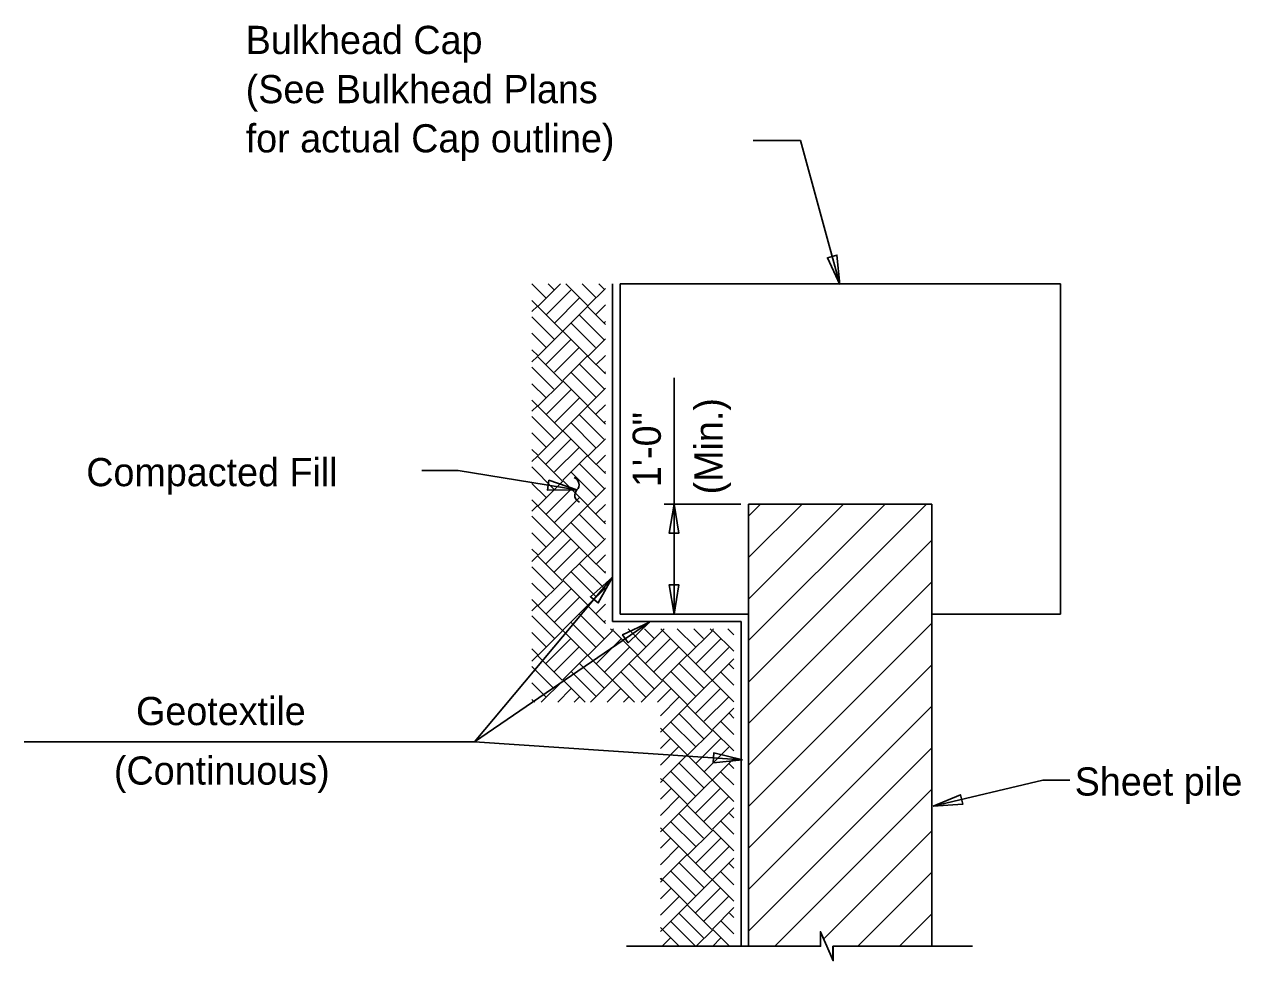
# Model space of a CAD drawing. Extents: x 0.4 to 30.4, y 0.1 to 19.4.
# Drawn here: x 8.54 to 15.06, y 14.4 to 19.42 of the extents above; entities that cross this region are included whole.
import ezdxf

# ---------------------------------------------------------------- set-up
doc = ezdxf.new("R2010")
doc.units = 0
for name, color, linetype in [('Dimension', 7, 'Continuous'), ('Miscellaneous', 7, 'Continuous'), ('Rebar', 7, 'Continuous'), ('SheetPileConc', 7, 'Continuous'), ('SheetPileConc_h', 7, 'Continuous'), ('TextStructures', 7, 'Continuous')]:
    doc.layers.add(name, color=color, linetype=linetype)

msp = doc.modelspace()

# ---------------------------------------------------------------- linework, layer by layer
at = {"layer": 'Dimension'}
for p, q in [((12.0243, 16.2579), (12.0243, 17.526)), ((12.3831, 16.8485), (11.9719, 16.8485)), ((11.8922, 16.2141), (10.9542, 15.5723)), ((12.3913, 15.4765), (10.9542, 15.5723)), ((11.7699, 14.4758), (12.738, 14.4758)), ((12.9487, 14.4758), (13.6252, 14.4758))]:
    msp.add_line(p, q, dxfattribs=at)
for points in [[(12.913, 18.0264), (12.7019, 18.7989), (12.4481, 18.7989)], [(11.5034, 16.9244), (10.8661, 17.0282), (10.6716, 17.0282)], [(11.6942, 16.4565), (10.9542, 15.5723), (8.5393, 15.5723)], [(13.4152, 15.2266), (14.0033, 15.3663), (14.1471, 15.3663)], [(12.738, 14.4758), (12.8099, 14.4758), (12.8099, 14.5539), (12.8768, 14.4028), (12.8768, 14.4758), (12.9487, 14.4758)], [(12.7383, 14.4758), (12.8108, 14.4758), (12.8108, 14.5533), (12.8446, 14.4758), (12.8783, 14.3983), (12.8783, 14.4758), (12.9508, 14.4758)]]:
    msp.add_lwpolyline(points, dxfattribs=at)
for points in [[(12.913, 18.0264), (12.8979, 18.1841), (12.8468, 18.1703)], [(11.5034, 16.9244), (11.3535, 16.9757), (11.345, 16.9234)], [(12.0243, 16.8485), (11.9978, 16.6923), (12.0507, 16.6923)], [(11.6942, 16.4565), (11.5762, 16.3508), (11.6176, 16.3178)], [(12.0243, 16.2579), (12.0507, 16.4141), (11.9978, 16.4141)], [(11.8922, 16.2141), (11.7485, 16.1474), (11.7785, 16.1038)], [(12.3913, 15.4765), (12.2372, 15.513), (12.2338, 15.4601)], [(13.4152, 15.2267), (13.5733, 15.2372), (13.561, 15.2886)]]:
    msp.add_lwpolyline(points, close=True, dxfattribs=at)
for centre, start, end in [((11.4742, 16.9527), 316.04656, 67.77378), ((11.5327, 16.8962), 136.04656, 247.77378)]:
    msp.add_arc(centre, 0.0406, start, end, dxfattribs=at)
at = {"layer": 'Miscellaneous'}
for p, q in [((11.2621, 18.0293), (11.3361, 17.9553)), ((11.4162, 18.0298), (11.2947, 17.9082)), ((11.3499, 18.0298), (11.3803, 17.9994)), ((11.5624, 17.9114), (11.444, 18.0298)), ((11.6065, 17.9555), (11.5323, 18.0298)), ((11.6507, 17.9998), (11.6208, 18.0298)), ((11.4716, 17.9966), (11.3389, 17.8639)), ((11.5157, 17.9524), (11.383, 17.8198)), ((11.6559, 18.0048), (11.5624, 17.9114)), ((11.2919, 17.911), (11.2621, 17.9408)), ((11.2919, 17.911), (11.2621, 17.8812)), ((11.5594, 17.6434), (11.2947, 17.9082)), ((11.5596, 17.9086), (11.2948, 17.6438)), ((11.5596, 17.9086), (11.6559, 17.8123)), ((11.6559, 17.9166), (11.6065, 17.8673)), ((11.3832, 17.7322), (11.2621, 17.8533)), ((11.4712, 17.8202), (11.6037, 17.6877)), ((11.5153, 17.8643), (11.6478, 17.7318)), ((11.6559, 17.8283), (11.6506, 17.8231)), ((11.3389, 17.688), (11.2621, 17.7648)), ((11.471, 17.7318), (11.3389, 17.5997)), ((11.5152, 17.6877), (11.383, 17.5556)), ((11.6559, 17.7342), (11.5622, 17.6406)), ((11.2948, 17.6438), (11.2621, 17.6766)), ((11.292, 17.641), (11.2621, 17.6111)), ((11.292, 17.641), (11.4246, 17.5085)), ((11.5594, 17.6434), (11.4273, 17.5113)), ((11.6559, 17.547), (11.5622, 17.6406)), ((11.6559, 17.6457), (11.6065, 17.5963)), ((11.2621, 17.5824), (11.3803, 17.4643)), ((11.6065, 17.4204), (11.4742, 17.5526)), ((11.6507, 17.4647), (11.5185, 17.5969)), ((11.6559, 17.5574), (11.6506, 17.5522)), ((11.2621, 17.4942), (11.3361, 17.4201)), ((11.4273, 17.5057), (11.2947, 17.3731)), ((11.5624, 17.3762), (11.4301, 17.5085)), ((11.4716, 17.4614), (11.3389, 17.3288)), ((11.6559, 17.4697), (11.5624, 17.3762)), ((11.2919, 17.3758), (11.2621, 17.4056)), ((11.2919, 17.3758), (11.2621, 17.3461)), ((11.5594, 17.1083), (11.2947, 17.3731)), ((11.5596, 17.3735), (11.2948, 17.1087)), ((11.5157, 17.4173), (11.383, 17.2847)), ((11.5596, 17.3735), (11.6559, 17.2772)), ((11.6559, 17.3815), (11.6065, 17.3321)), ((11.3832, 17.1971), (11.2621, 17.3182)), ((11.5153, 17.3292), (11.6478, 17.1967)), ((11.6559, 17.2932), (11.6506, 17.288)), ((11.3389, 17.1529), (11.2621, 17.2297)), ((11.4712, 17.2851), (11.6037, 17.1525)), ((11.471, 17.1967), (11.3389, 17.0646)), ((11.6559, 17.1991), (11.5622, 17.1055)), ((11.2948, 17.1087), (11.2621, 17.1414)), ((11.292, 17.1059), (11.2621, 17.076)), ((11.292, 17.1059), (11.4246, 16.9734)), ((11.5152, 17.1525), (11.383, 17.0205)), ((11.5594, 17.1083), (11.4273, 16.9762)), ((11.6559, 17.0119), (11.5622, 17.1055)), ((11.6559, 17.1106), (11.6065, 17.0612)), ((11.2621, 17.0473), (11.3803, 16.9291)), ((11.6507, 16.9295), (11.5185, 17.0618)), ((11.4273, 16.9706), (11.2947, 16.8379)), ((11.5624, 16.8411), (11.4301, 16.9734)), ((11.6065, 16.8853), (11.4742, 17.0175)), ((11.6559, 17.0223), (11.6506, 17.0171)), ((11.2621, 16.9591), (11.3361, 16.885)), ((11.4716, 16.9263), (11.3389, 16.7937)), ((11.6559, 16.9346), (11.5624, 16.8411)), ((11.2919, 16.8407), (11.2621, 16.8705)), ((11.2919, 16.8407), (11.2621, 16.8109)), ((11.5594, 16.5732), (11.2947, 16.8379)), ((11.5596, 16.8384), (11.2948, 16.5736)), ((11.5157, 16.8822), (11.383, 16.7495)), ((11.5596, 16.8384), (11.6559, 16.7421)), ((11.6559, 16.8464), (11.6065, 16.797)), ((12.4236, 16.5612), (12.7109, 16.8485)), ((12.4236, 16.3385), (12.9336, 16.8485)), ((12.4236, 16.1158), (13.1564, 16.8485)), ((12.4236, 15.8931), (13.3791, 16.8485)), ((12.4236, 16.7839), (12.4882, 16.8485)), ((11.3832, 16.662), (11.2621, 16.7831)), ((11.5153, 16.7941), (11.6478, 16.6616)), ((11.4712, 16.75), (11.6037, 16.6174)), ((11.6559, 16.7581), (11.6506, 16.7529)), ((11.3389, 16.6177), (11.2621, 16.6946)), ((11.471, 16.6616), (11.3389, 16.5295)), ((11.6559, 16.664), (11.5622, 16.5704)), ((12.4236, 15.6703), (13.408, 16.6547)), ((11.2948, 16.5736), (11.2621, 16.6063)), ((11.5152, 16.6174), (11.383, 16.4853)), ((11.5594, 16.5732), (11.4273, 16.441)), ((11.6559, 16.5755), (11.6065, 16.5261)), ((11.292, 16.5708), (11.2621, 16.5409)), ((11.2621, 16.5122), (11.3803, 16.394)), ((11.292, 16.5708), (11.4246, 16.4383)), ((11.6507, 16.3944), (11.5185, 16.5267)), ((11.6559, 16.4768), (11.5622, 16.5704)), ((11.6065, 16.3501), (11.4742, 16.4824)), ((11.6559, 16.4872), (11.6506, 16.482)), ((11.2621, 16.4239), (11.3361, 16.3499)), ((11.4273, 16.4355), (11.2947, 16.3028)), ((11.4716, 16.3912), (11.3389, 16.2585)), ((11.5624, 16.306), (11.4301, 16.4383)), ((11.6559, 16.3995), (11.5624, 16.306)), ((12.4236, 15.4475), (13.408, 16.4319)), ((11.2919, 16.3056), (11.2621, 16.3354)), ((11.5157, 16.3471), (11.383, 16.2144)), ((11.2919, 16.3056), (11.2621, 16.2758)), ((11.3832, 16.1269), (11.2621, 16.248)), ((11.5594, 16.038), (11.2947, 16.3028)), ((11.5596, 16.3032), (11.2948, 16.0384)), ((11.5153, 16.2589), (11.6478, 16.1264)), ((11.5596, 16.3032), (11.6559, 16.207)), ((11.6559, 16.3112), (11.6065, 16.2619)), ((11.4712, 16.2148), (11.6037, 16.0823)), ((11.6559, 16.223), (11.6506, 16.2178)), ((12.4236, 15.2248), (13.408, 16.2092)), ((11.3389, 16.0826), (11.2621, 16.1594)), ((11.471, 16.1264), (11.3389, 15.9943)), ((11.6949, 16.1679), (11.5622, 16.0353)), ((11.7391, 16.1236), (11.6065, 15.991)), ((11.6837, 16.1792), (11.6921, 16.1707)), ((11.7005, 16.1792), (11.6949, 16.1735)), ((11.8299, 16.0384), (11.6977, 16.1707)), ((11.874, 16.0826), (11.7775, 16.1792)), ((11.9706, 16.1792), (11.8299, 16.0384)), ((11.9183, 16.1269), (11.866, 16.1792)), ((12.0062, 16.1264), (11.874, 15.9943)), ((12.0946, 16.038), (11.9534, 16.1792)), ((12.042, 16.1792), (12.1388, 16.0823)), ((12.23, 16.1679), (12.0974, 16.0353)), ((12.1302, 16.1792), (12.1829, 16.1264)), ((12.2743, 16.1236), (12.1416, 15.991)), ((12.2188, 16.1792), (12.2272, 16.1707)), ((12.2357, 16.1792), (12.23, 16.1735)), ((12.3449, 16.0586), (12.2328, 16.1707)), ((12.3449, 16.1469), (12.3126, 16.1792)), ((11.2948, 16.0384), (11.2621, 16.0711)), ((11.5152, 16.0823), (11.383, 15.9502)), ((11.7833, 16.0795), (11.6506, 15.9469)), ((12.0503, 16.0823), (11.9182, 15.9502)), ((12.3184, 16.0795), (12.1857, 15.9469)), ((11.292, 16.0357), (11.2621, 16.0058)), ((11.292, 16.0357), (11.4246, 15.9031)), ((11.5594, 16.038), (11.4273, 15.9059)), ((11.6507, 15.8593), (11.5185, 15.9916)), ((11.8121, 15.7854), (11.5622, 16.0353)), ((11.8272, 16.0357), (11.5768, 15.7854)), ((11.7829, 15.9914), (11.9154, 15.8589)), ((11.8272, 16.0357), (11.9597, 15.9031)), ((12.0946, 16.038), (11.9624, 15.9059)), ((12.1859, 15.8593), (12.0536, 15.9916)), ((12.3449, 15.7877), (12.0974, 16.0353)), ((12.3449, 16.0183), (12.0975, 15.7709)), ((12.318, 15.9914), (12.3449, 15.9645)), ((12.4236, 15.0021), (13.408, 15.9865)), ((11.2621, 15.977), (11.3803, 15.8589)), ((11.6065, 15.815), (11.4742, 15.9473)), ((11.7387, 15.9473), (11.8713, 15.8147)), ((12.1416, 15.815), (12.0093, 15.9473)), ((12.2739, 15.9473), (12.3449, 15.8762)), ((11.2621, 15.8888), (11.3361, 15.8147)), ((11.4273, 15.9004), (11.3124, 15.7854)), ((11.4716, 15.8561), (11.4009, 15.7854)), ((11.5478, 15.7854), (11.4301, 15.9031)), ((11.7386, 15.8589), (11.6651, 15.7854)), ((11.9624, 15.9004), (11.8475, 15.7854)), ((12.0067, 15.8561), (11.9361, 15.7854)), ((12.0975, 15.7709), (11.9652, 15.9031)), ((12.2737, 15.8589), (12.1416, 15.7268)), ((11.2769, 15.7854), (11.2621, 15.8003)), ((11.5157, 15.812), (11.4891, 15.7854)), ((11.7827, 15.8147), (11.7534, 15.7854)), ((12.0509, 15.812), (11.9512, 15.7122)), ((12.3178, 15.8147), (12.1857, 15.6826)), ((12.0947, 15.7681), (11.9512, 15.6245)), ((12.0947, 15.7681), (12.2272, 15.6356)), ((12.3449, 15.7532), (12.23, 15.6384)), ((12.4236, 14.7794), (13.408, 15.7637)), ((12.0063, 15.6797), (12.1388, 15.5472)), ((12.0504, 15.7238), (12.1829, 15.5913)), ((12.3449, 15.6118), (12.2769, 15.6797)), ((12.3449, 15.7003), (12.3212, 15.724)), ((12.0946, 15.5029), (11.9512, 15.6463)), ((12.23, 15.6328), (12.0974, 15.5001)), ((12.3449, 15.5235), (12.2328, 15.6356)), ((12.0062, 15.5913), (11.9512, 15.5363)), ((12.0503, 15.5472), (11.9512, 15.448)), ((12.2743, 15.5885), (12.1416, 15.4559)), ((12.3184, 15.5444), (12.1857, 15.4117)), ((12.4236, 14.5566), (13.408, 15.541)), ((12.0946, 15.5029), (11.9624, 15.3708)), ((12.3449, 15.2526), (12.0974, 15.5001)), ((12.3449, 15.4832), (12.0975, 15.2358)), ((12.1416, 15.2799), (12.0093, 15.4122)), ((12.1859, 15.3242), (12.0536, 15.4564)), ((12.2739, 15.4122), (12.3449, 15.3411)), ((12.318, 15.4563), (12.3449, 15.4294)), ((11.9512, 15.3766), (11.9597, 15.368)), ((11.9624, 15.3653), (11.9512, 15.3539)), ((12.0975, 15.2358), (11.9652, 15.368)), ((12.0067, 15.321), (11.9512, 15.2654)), ((12.0509, 15.2768), (11.9512, 15.1771)), ((12.2737, 15.3237), (12.1416, 15.1917)), ((12.3178, 15.2796), (12.1857, 15.1475)), ((12.5655, 14.4758), (13.408, 15.3183)), ((12.0947, 15.233), (11.9512, 15.0894)), ((12.0947, 15.233), (12.2272, 15.1005)), ((12.3449, 15.2181), (12.23, 15.1032)), ((12.0063, 15.1446), (12.1388, 15.0121)), ((12.0504, 15.1887), (12.1829, 15.0562)), ((12.3449, 15.0766), (12.2769, 15.1446)), ((12.3449, 15.1651), (12.3212, 15.1888)), ((12.0946, 14.9678), (11.9512, 15.1112)), ((12.23, 15.0976), (12.0974, 14.965)), ((12.3449, 14.9884), (12.2328, 15.1005)), ((12.8273, 14.5148), (13.408, 15.0955)), ((12.0062, 15.0562), (11.9512, 15.0012)), ((12.0503, 15.0121), (11.9512, 14.9129)), ((12.2743, 15.0534), (12.1416, 14.9207)), ((12.3184, 15.0093), (12.1857, 14.8766)), ((12.0946, 14.9678), (11.9624, 14.8357)), ((12.3449, 14.7174), (12.0974, 14.965)), ((12.3449, 14.9481), (12.0975, 14.7006)), ((12.1416, 14.7448), (12.0093, 14.877)), ((12.1859, 14.7891), (12.0536, 14.9213)), ((12.2739, 14.877), (12.3449, 14.806)), ((12.318, 14.9211), (12.3449, 14.8943)), ((11.9512, 14.8414), (11.9597, 14.8329)), ((11.9624, 14.8301), (11.9512, 14.8188)), ((12.0975, 14.7006), (11.9652, 14.8329)), ((13.011, 14.4758), (13.408, 14.8728)), ((12.0067, 14.7858), (11.9512, 14.7303)), ((12.2737, 14.7886), (12.1416, 14.6565)), ((12.0509, 14.7417), (11.9512, 14.642)), ((12.0947, 14.6979), (11.9512, 14.5543)), ((12.0947, 14.6979), (12.2272, 14.5653)), ((12.3178, 14.7445), (12.1857, 14.6124)), ((12.3449, 14.683), (12.23, 14.5681)), ((12.0504, 14.6536), (12.1829, 14.5211)), ((12.3449, 14.63), (12.3212, 14.6537)), ((13.2338, 14.4758), (13.408, 14.65)), ((12.0514, 14.4758), (11.9512, 14.5761)), ((12.0063, 14.6095), (12.1388, 14.4769)), ((12.23, 14.5625), (12.1432, 14.4758)), ((12.3224, 14.4758), (12.2328, 14.5653)), ((12.3449, 14.5415), (12.2769, 14.6095)), ((12.0062, 14.5211), (11.9609, 14.4758)), ((12.2743, 14.5183), (12.2318, 14.4758)), ((12.0503, 14.4769), (12.0491, 14.4758))]:
    msp.add_line(p, q, dxfattribs=at)
at = {"layer": 'Rebar'}
for p, q in [((11.6952, 16.2185), (11.6952, 18.0298)), ((12.3842, 16.2185), (11.6952, 16.2185)), ((12.3842, 14.4758), (12.3842, 16.2185))]:
    msp.add_line(p, q, dxfattribs=at)
at = {"layer": 'SheetPileConc'}
for p, q in [((12.4236, 14.4758), (12.4236, 16.8485)), ((12.4236, 16.8485), (13.408, 16.8485)), ((13.408, 16.8485), (13.408, 14.4758))]:
    msp.add_line(p, q, dxfattribs=at)
at = {"layer": 'SheetPileConc_h'}
for p, q in [((11.7346, 16.2579), (11.7346, 18.0298)), ((11.7346, 18.0298), (14.0971, 18.0298)), ((14.0971, 18.0298), (14.0971, 16.2579)), ((12.4237, 16.2579), (11.7346, 16.2579)), ((13.408, 16.2579), (14.0971, 16.2579))]:
    msp.add_line(p, q, dxfattribs=at)

# ---------------------------------------------------------------- texts
at = {"layer": 'Dimension'}
for s, p in [('Bulkhead Cap', (9.7268, 19.2632)), ('(See Bulkhead Plans', (9.7268, 18.9992)), ('for actual Cap outline)', (9.7268, 18.7352)), ('Geotextile', (9.1385, 15.6622)), ('(Continuous)', (9.0199, 15.343))]:
    msp.add_text(s, height=0.1512, dxfattribs=at).set_placement(p)
at = {"layer": 'TextStructures'}
for s, p in [('(Min.)', (12.2848, 16.9001)), ('1\'-0"', (11.9536, 16.9394))]:
    msp.add_text(s, height=0.1512, rotation=90, dxfattribs=at).set_placement(p)
for s, p in [('Compacted Fill', (8.8715, 16.9442)), ('Sheet pile', (14.1736, 15.2842))]:
    msp.add_text(s, height=0.1512, dxfattribs=at).set_placement(p)

doc.saveas('drawing.dxf')
